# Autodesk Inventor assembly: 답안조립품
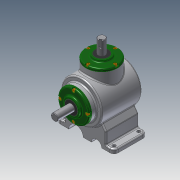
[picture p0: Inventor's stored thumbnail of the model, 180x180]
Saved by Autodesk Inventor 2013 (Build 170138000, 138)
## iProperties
Created: 2018-08
Part Number: 답안조립품
Document SubType Name: Assembly
Designer: Administrator
Author: Administrator
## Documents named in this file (16)
- C:\Users\Administrator\Desktop\480808V1025\답안조립품.iam
- C:\Users\Administrator\Desktop\480808V1025\본체.ipt
- C:\Users\Administrator\Desktop\480808V1025\메인 축 - 복사본.ipt
- 메인 축.ipt
- C:\Users\Administrator\Desktop\480808V1025\베어링 6203 - 복사본.ipt
- C:\Users\Administrator\Desktop\480808V1025\베어링 6203.ipt
- C:\Users\Administrator\Desktop\480808V1025\볼트 M4 - 복사본.ipt
- C:\Users\Administrator\Desktop\480808V1025\볼트 M4.ipt
- C:\Users\Administrator\Desktop\480808V1025\서브 축.ipt
- 서브 축.ipt
- C:\Users\Administrator\Desktop\480808V1025\오일실 17 32 8.ipt
- C:\Users\Administrator\Desktop\480808V1025\커버.ipt
- C:\Users\Administrator\Desktop\480808V1025\키 4x4.ipt
- C:\Users\Administrator\Desktop\480808V1025\키 5x5.ipt
- C:\Users\Administrator\Desktop\480808V1025\메인 베벨기어.ipt
- C:\Users\Administrator\Desktop\480808V1025\서브 베벨기어.ipt
